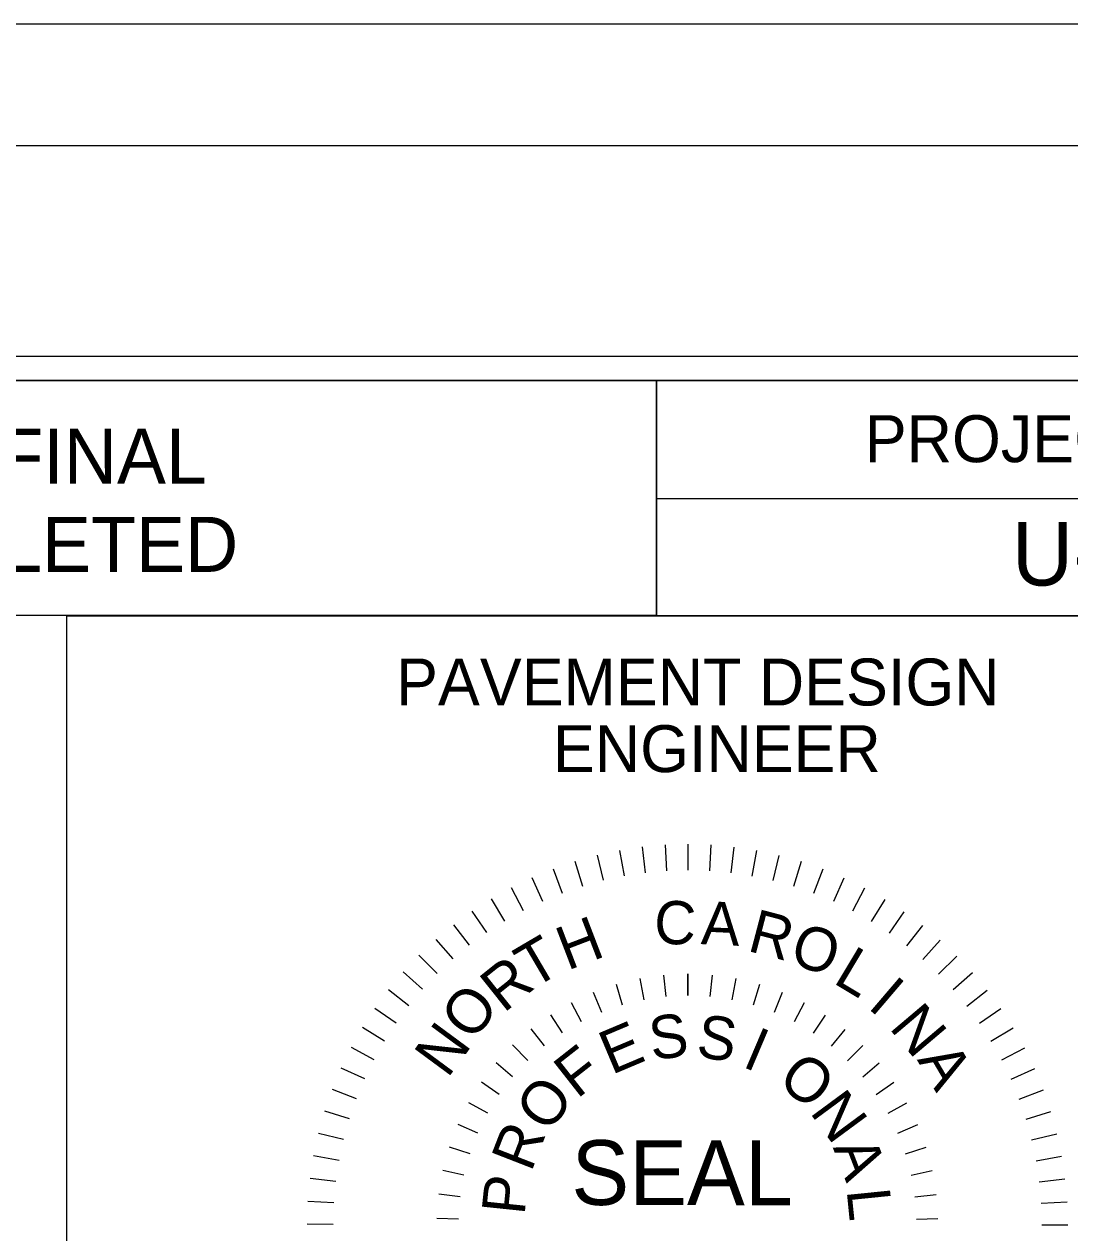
# Model space of a CAD drawing. Extents: x 2294455 to 2294842, y 719496 to 719941.
# Drawn here: x 2294734.45 to 2294756.72, y 719693.01 to 719718.76 of the extents above; entities that cross this region are included whole.
import ezdxf

# ---------------------------------------------------------------- set-up
doc = ezdxf.new("R2010")
doc.units = 0
for name, color, linetype in [('Default', 7, 'Continuous'), ('Sheet Cutting Line CELL', 7, 'Continuous'), ('Sheet Data Field CELL', 7, 'Continuous'), ('Sheet Plan CELL', 7, 'Continuous'), ('Sheet Plot Border Inside CELL', 7, 'Continuous'), ('Sheet Plot Border Outside CELL', 7, 'Continuous'), ('Sheet Sticker Exception Certification CELL', 7, 'Continuous'), ('Sheet Typical CELL', 7, 'Continuous')]:
    doc.layers.add(name, color=color, linetype=linetype)

msp = doc.modelspace()

# ---------------------------------------------------------------- linework, layer by layer
at = {"layer": 'Default'}
for p, q in [((2294747.127, 719701.161), (2294747.226, 719700.618)), ((2294747.611, 719701.233), (2294747.676, 719700.686)), ((2294748.098, 719701.277), (2294748.13, 719700.726)), ((2294748.587, 719701.291), (2294748.587, 719700.739)), ((2294749.077, 719701.276), (2294749.043, 719700.725)), ((2294749.564, 719701.23), (2294749.497, 719700.683)), ((2294750.047, 719701.157), (2294749.947, 719700.614)), ((2294746.177, 719700.928), (2294746.34, 719700.4)), ((2294746.649, 719701.059), (2294746.779, 719700.523)), ((2294750.525, 719701.053), (2294750.393, 719700.518)), ((2294750.997, 719700.922), (2294750.832, 719700.394)), ((2294745.262, 719700.582), (2294745.488, 719700.078)), ((2294745.714, 719700.769), (2294745.91, 719700.252)), ((2294751.459, 719700.761), (2294751.262, 719700.245)), ((2294744.822, 719700.369), (2294745.078, 719699.879)), ((2294751.91, 719700.572), (2294751.684, 719700.07)), ((2294752.35, 719700.358), (2294752.093, 719699.869)), ((2294744.395, 719700.129), (2294744.68, 719699.656)), ((2294752.777, 719700.117), (2294752.49, 719699.645)), ((2294743.984, 719699.864), (2294744.297, 719699.409)), ((2294753.187, 719699.851), (2294752.873, 719699.397)), ((2294743.59, 719699.575), (2294743.929, 719699.14)), ((2294753.58, 719699.561), (2294753.239, 719699.126)), ((2294743.213, 719699.262), (2294743.579, 719698.848)), ((2294753.956, 719699.246), (2294753.589, 719698.834)), ((2294742.857, 719698.927), (2294743.246, 719698.536)), ((2294754.311, 719698.91), (2294753.921, 719698.521)), ((2294742.521, 719698.571), (2294742.933, 719698.205)), ((2294748.583, 719698.53), (2294748.583, 719698.07)), ((2294748.583, 719698.07), (2294748.583, 719698.53)), ((2294754.646, 719698.554), (2294754.233, 719698.188)), ((2294747.057, 719698.309), (2294747.187, 719697.868)), ((2294747.558, 719698.432), (2294747.645, 719697.98)), ((2294748.068, 719698.505), (2294748.112, 719698.048)), ((2294749.099, 719698.504), (2294749.054, 719698.046)), ((2294749.609, 719698.429), (2294749.52, 719697.977)), ((2294750.109, 719698.305), (2294749.978, 719697.864)), ((2294742.207, 719698.195), (2294742.641, 719697.855)), ((2294746.57, 719698.139), (2294746.742, 719697.712)), ((2294750.596, 719698.133), (2294750.422, 719697.707)), ((2294754.959, 719698.177), (2294754.524, 719697.838)), ((2294741.916, 719697.802), (2294742.37, 719697.488)), ((2294746.102, 719697.922), (2294746.314, 719697.514)), ((2294751.064, 719697.915), (2294750.85, 719697.508)), ((2294755.249, 719697.783), (2294754.794, 719697.47)), ((2294745.656, 719697.661), (2294745.908, 719697.275)), ((2294751.508, 719697.653), (2294751.255, 719697.268)), ((2294741.65, 719697.392), (2294742.122, 719697.105)), ((2294745.238, 719697.358), (2294745.527, 719696.999)), ((2294751.925, 719697.349), (2294751.636, 719696.99)), ((2294755.514, 719697.372), (2294755.041, 719697.087)), ((2294744.852, 719697.017), (2294745.174, 719696.687)), ((2294752.31, 719697.006), (2294751.988, 719696.677)), ((2294741.409, 719696.966), (2294741.898, 719696.708)), ((2294755.754, 719696.945), (2294755.264, 719696.689)), ((2294741.195, 719696.526), (2294741.697, 719696.299)), ((2294744.501, 719696.64), (2294744.851, 719696.343)), ((2294752.661, 719696.628), (2294752.309, 719696.332)), ((2294755.967, 719696.505), (2294755.463, 719696.28)), ((2294744.186, 719696.23), (2294744.565, 719695.968)), ((2294752.974, 719696.218), (2294752.595, 719695.956)), ((2294741.006, 719696.074), (2294741.522, 719695.877)), ((2294756.154, 719696.053), (2294755.637, 719695.857)), ((2294743.914, 719695.793), (2294744.315, 719695.568)), ((2294753.245, 719695.78), (2294752.843, 719695.556)), ((2294740.845, 719695.612), (2294741.373, 719695.447)), ((2294756.313, 719695.591), (2294755.785, 719695.427)), ((2294743.684, 719695.33), (2294744.106, 719695.146)), ((2294753.474, 719695.316), (2294753.051, 719695.133)), ((2294740.714, 719695.14), (2294741.25, 719695.008)), ((2294756.444, 719695.118), (2294755.907, 719694.988)), ((2294740.61, 719694.663), (2294741.153, 719694.563)), ((2294743.501, 719694.848), (2294743.939, 719694.706)), ((2294753.655, 719694.833), (2294753.217, 719694.693)), ((2294756.546, 719694.64), (2294756.003, 719694.541)), ((2294740.537, 719694.179), (2294741.084, 719694.112)), ((2294743.365, 719694.351), (2294743.814, 719694.251)), ((2294753.79, 719694.336), (2294753.341, 719694.237)), ((2294756.618, 719694.156), (2294756.07, 719694.091)), ((2294740.491, 719693.692), (2294741.042, 719693.658)), ((2294743.277, 719693.842), (2294743.733, 719693.787)), ((2294753.876, 719693.827), (2294753.42, 719693.773)), ((2294756.662, 719693.669), (2294756.111, 719693.637)), ((2294740.476, 719693.203), (2294741.028, 719693.202)), ((2294743.239, 719693.328), (2294743.699, 719693.316)), ((2294753.913, 719693.313), (2294753.454, 719693.302)), ((2294756.676, 719693.18), (2294756.124, 719693.18))]:
    msp.add_line(p, q, dxfattribs=at)
at = {"layer": 'Sheet Cutting Line CELL'}
msp.add_line((2294791.324, 719716.169), (2294454.524, 719716.169), dxfattribs=at)
at = {"layer": 'Sheet Plan CELL'}
msp.add_lwpolyline([(2294761.64, 719683.659), (2294735.355, 719683.659), (2294735.355, 719706.159), (2294761.64, 719706.159)], dxfattribs=at)
at = {"layer": 'Sheet Plot Border Inside CELL'}
msp.add_lwpolyline([(2294790.424, 719711.679), (2294457.124, 719711.679), (2294457.124, 719500.659), (2294790.424, 719500.659)], close=True, dxfattribs=at)
at = {"layer": 'Sheet Plot Border Outside CELL'}
for points in [[(2294793.79, 719718.758), (2294456.99, 719718.758), (2294456.99, 719498.758), (2294793.79, 719498.758)], [(2294791.324, 719716.169), (2294454.524, 719716.169), (2294454.524, 719496.169), (2294791.324, 719496.169)]]:
    msp.add_lwpolyline(points, close=True, dxfattribs=at)
at = {"layer": 'Sheet Sticker Exception Certification CELL'}
for p, q in [((2294705.291, 719711.172), (2294747.914, 719711.172)), ((2294747.914, 719711.169), (2294747.914, 719706.162)), ((2294747.914, 719706.165), (2294705.291, 719706.165))]:
    msp.add_line(p, q, dxfattribs=at)
at = {"layer": 'Sheet Typical CELL'}
for p, q in [((2294747.914, 719708.659), (2294787.924, 719708.659)), ((2294747.914, 719706.159), (2294767.924, 719706.159))]:
    msp.add_line(p, q, dxfattribs=at)
for points in [[(2294787.924, 719711.169), (2294487.924, 719711.169), (2294487.924, 719501.169), (2294787.924, 719501.169)], [(2294747.914, 719711.169), (2294787.924, 719711.169), (2294787.924, 719706.159), (2294747.914, 719706.159)]]:
    msp.add_lwpolyline(points, close=True, dxfattribs=at)

# ---------------------------------------------------------------- texts
at = {"layer": 'Default'}
for s, height, rotation, p in [('C', 0.92, 357.2756, (2294747.849, 719699.184)), ('A', 0.92, 357.2756, (2294748.854, 719699.165)), ('R', 0.924, 345.2663, (2294749.827, 719699.027)), ('H', 0.928, 20.9863, (2294746.018, 719698.596)), ('O', 0.926, 342.2095, (2294750.718, 719698.762)), ('T', 0.934, 30.4182, (2294745.277, 719698.197)), ('L', 0.935, 329.0732, (2294751.653, 719698.351)), ('R', 0.939, 38.5792, (2294744.658, 719697.683)), ('I', 0.939, 319.4977, (2294752.393, 719697.816)), ('O', 0.94, 51.6359, (2294743.991, 719697.065)), ('N', 0.94, 310.2033, (2294752.854, 719697.382)), ('N', 0.939, 53.5954, (2294743.462, 719696.289)), ('E', 0.929, 22.863, (2294746.958, 719696.374)), ('S', 0.921, 7.5668, (2294747.822, 719696.688)), ('S', 0.921, 352.2705, (2294748.741, 719696.764)), ('I', 0.929, 336.9743, (2294749.718, 719696.564)), ('F', 0.938, 38.1593, (2294746.222, 719695.855)), ('O', 0.939, 321.678, (2294750.459, 719696.205)), ('A', 0.937, 300.4357, (2294753.46, 719696.702)), ('O', 0.939, 53.4555, (2294745.609, 719695.114)), ('N', 0.939, 306.3818, (2294751.166, 719695.588)), ('R', 0.93, 68.7517, (2294745.244, 719694.289)), ('SEAL', 1.3802, 359.9186, (2294746.103, 719693.609)), ('A', 0.93, 291.0855, (2294751.669, 719694.834)), ('P', 0.92, 84.048, (2294745.104, 719693.377)), ('L', 0.92, 275.7893, (2294751.966, 719693.923))]:
    msp.add_text(s, height=height, rotation=rotation, dxfattribs=at).set_placement(p)
at = {"layer": 'Sheet Data Field CELL'}
msp.add_text('U-4700CA', height=1.35, rotation=360, dxfattribs=at).set_placement((2294755.487, 719706.802))
at = {"layer": 'Sheet Plan CELL'}
for s, height, p in [('PAVEMENT DESIGN', 1.00002, (2294742.369, 719704.247)), ('ENGINEER', 1, (2294745.711, 719702.827))]:
    msp.add_text(s, height=height, dxfattribs=at).set_placement(p)
at = {"layer": 'Sheet Sticker Exception Certification CELL'}
for s, p in [('DOCUMENT NOT CONSIDERED FINAL', (2294709.781, 719708.968)), ('UNLESS ALL SIGNATURES COMPLETED', (2294708.7, 719707.093))]:
    msp.add_text(s, height=1.17193, dxfattribs=at).set_placement(p)
at = {"layer": 'Sheet Typical CELL'}
msp.add_text('PROJECT REFERENCE NO.', height=1.00002, dxfattribs=at).set_placement((2294752.354, 719709.429))

doc.saveas('drawing.dxf')
